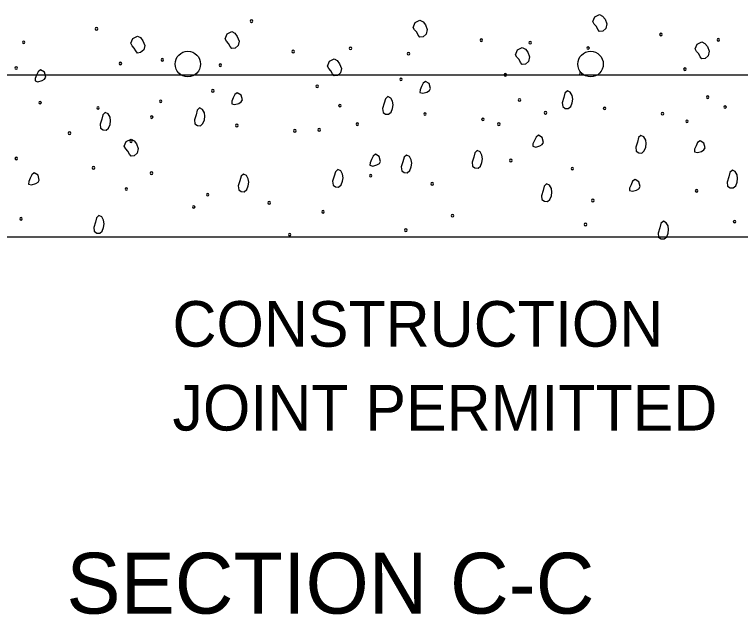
# Model space of a CAD drawing. Extents: x -439.1 to -407.9, y -458.1 to -436.2.
# Drawn here: x -421.545 to -419.155, y -450.306 to -448.332 of the extents above; entities that cross this region are included whole.
import ezdxf

# ---------------------------------------------------------------- set-up
doc = ezdxf.new("R2010")
doc.units = 0
doc.layers.add('Level 4', color=7, linetype='Continuous')

msp = doc.modelspace()

# ---------------------------------------------------------------- linework, layer by layer
at = {"layer": 'Level 4'}
for p, q in [((-423.8016, -448.5298), (-417.0312, -448.5298)), ((-423.8016, -449.0632), (-416.8905, -449.0632))]:
    msp.add_line(p, q, dxfattribs=at)
for points in [[(-420.2324, -448.3737), (-420.2258, -448.3579), (-420.2103, -448.3503), (-420.2, -448.3552), (-420.1921, -448.3659), (-420.1864, -448.3811), (-420.1896, -448.3957), (-420.1996, -448.4046), (-420.2103, -448.4061), (-420.2158, -448.3991), (-420.2207, -448.3892), (-420.2277, -448.3817), (-420.2324, -448.3737)], [(-419.6411, -448.3549), (-419.6345, -448.3392), (-419.619, -448.3315), (-419.6087, -448.3364), (-419.6008, -448.3471), (-419.5951, -448.3624), (-419.5982, -448.377), (-419.6083, -448.3858), (-419.619, -448.3873), (-419.6244, -448.3803), (-419.6294, -448.3705), (-419.6364, -448.3629), (-419.6411, -448.3549)], [(-420.8519, -448.4112), (-420.8453, -448.3955), (-420.8298, -448.3878), (-420.8195, -448.3927), (-420.8116, -448.4034), (-420.8059, -448.4187), (-420.809, -448.4333), (-420.8191, -448.4421), (-420.8298, -448.4437), (-420.8353, -448.4366), (-420.8402, -448.4268), (-420.8472, -448.4192), (-420.8519, -448.4112)], [(-421.1625, -448.4261), (-421.1559, -448.4104), (-421.1404, -448.4028), (-421.1301, -448.4076), (-421.1222, -448.4183), (-421.1165, -448.4336), (-421.1196, -448.4482), (-421.1297, -448.457), (-421.1404, -448.4586), (-421.1459, -448.4515), (-421.1508, -448.4417), (-421.1578, -448.4341), (-421.1625, -448.4261)], [(-419.304, -448.4449), (-419.2974, -448.4292), (-419.2819, -448.4215), (-419.2717, -448.4264), (-419.2638, -448.4371), (-419.2581, -448.4524), (-419.2612, -448.467), (-419.2712, -448.4758), (-419.2819, -448.4774), (-419.2874, -448.4703), (-419.2923, -448.4605), (-419.2993, -448.4529), (-419.304, -448.4449)], [(-419.8953, -448.4637), (-419.8888, -448.4479), (-419.8733, -448.4403), (-419.863, -448.4452), (-419.8551, -448.4559), (-419.8494, -448.4711), (-419.8525, -448.4857), (-419.8626, -448.4946), (-419.8733, -448.4961), (-419.8787, -448.4891), (-419.8837, -448.4792), (-419.8907, -448.4717), (-419.8953, -448.4637)], [(-420.5148, -448.5012), (-420.5083, -448.4855), (-420.4928, -448.4778), (-420.4825, -448.4827), (-420.4746, -448.4934), (-420.4689, -448.5087), (-420.472, -448.5233), (-420.482, -448.5321), (-420.4928, -448.5337), (-420.4982, -448.5266), (-420.5032, -448.5168), (-420.5102, -448.5092), (-420.5148, -448.5012)], [(-421.4593, -448.5139), (-421.4671, -448.5198), (-421.4723, -448.5308), (-421.477, -448.542), (-421.4775, -448.5502), (-421.468, -448.5526), (-421.4541, -448.5489), (-421.4463, -448.5442), (-421.4424, -448.5373), (-421.4467, -448.5213), (-421.4593, -448.5139)], [(-420.1922, -448.5514), (-420.1999, -448.5573), (-420.2051, -448.5683), (-420.2099, -448.5795), (-420.2103, -448.5878), (-420.2009, -448.5901), (-420.187, -448.5865), (-420.1792, -448.5817), (-420.1753, -448.5748), (-420.1795, -448.5589), (-420.1922, -448.5514)], [(-420.8116, -448.589), (-420.8194, -448.5949), (-420.8246, -448.6058), (-420.8294, -448.6171), (-420.8298, -448.6253), (-420.8203, -448.6277), (-420.8065, -448.624), (-420.7987, -448.6193), (-420.7948, -448.6123), (-420.799, -448.5964), (-420.8116, -448.589)], [(-419.7247, -448.5828), (-419.7326, -448.5902), (-419.7363, -448.6048), (-419.7416, -448.6216), (-419.7402, -448.6347), (-419.732, -448.6403), (-419.7221, -448.6412), (-419.7136, -448.6338), (-419.7091, -448.6217), (-419.7073, -448.61), (-419.7091, -448.5983), (-419.7151, -448.5875), (-419.7247, -448.5828)], [(-420.316, -448.6015), (-420.3239, -448.609), (-420.3277, -448.6236), (-420.333, -448.6404), (-420.3316, -448.6535), (-420.3234, -448.6591), (-420.3134, -448.6599), (-420.305, -448.6526), (-420.3004, -448.6405), (-420.2986, -448.6287), (-420.3004, -448.6171), (-420.3064, -448.6063), (-420.316, -448.6015)], [(-421.2461, -448.654), (-421.254, -448.6614), (-421.2578, -448.6761), (-421.2631, -448.6928), (-421.2617, -448.7059), (-421.2535, -448.7115), (-421.2435, -448.7124), (-421.2351, -448.705), (-421.2305, -448.6929), (-421.2287, -448.6812), (-421.2305, -448.6696), (-421.2365, -448.6588), (-421.2461, -448.654)], [(-420.9355, -448.6391), (-420.9434, -448.6465), (-420.9472, -448.6611), (-420.9525, -448.6779), (-420.9511, -448.691), (-420.9429, -448.6966), (-420.9329, -448.6975), (-420.9245, -448.6901), (-420.9199, -448.678), (-420.9181, -448.6663), (-420.9199, -448.6547), (-420.9259, -448.6438), (-420.9355, -448.6391)], [(-419.8202, -448.7289), (-419.828, -448.7348), (-419.8332, -448.7458), (-419.838, -448.757), (-419.8384, -448.7652), (-419.8289, -448.7676), (-419.815, -448.7639), (-419.8073, -448.7592), (-419.8034, -448.7523), (-419.8076, -448.7363), (-419.8202, -448.7289)], [(-419.4824, -448.7291), (-419.4903, -448.7365), (-419.4941, -448.7512), (-419.4994, -448.7679), (-419.498, -448.781), (-419.4898, -448.7866), (-419.4798, -448.7875), (-419.4714, -448.7801), (-419.4668, -448.768), (-419.465, -448.7563), (-419.4668, -448.7447), (-419.4728, -448.7339), (-419.4824, -448.7291)], [(-421.1835, -448.7651), (-421.177, -448.7494), (-421.1615, -448.7417), (-421.1512, -448.7466), (-421.1433, -448.7573), (-421.1376, -448.7726), (-421.1407, -448.7872), (-421.1508, -448.796), (-421.1615, -448.7975), (-421.1669, -448.7905), (-421.1719, -448.7807), (-421.1789, -448.7731), (-421.1835, -448.7651)], [(-419.2881, -448.7469), (-419.2959, -448.7528), (-419.3011, -448.7638), (-419.3059, -448.775), (-419.3063, -448.7832), (-419.2968, -448.7856), (-419.2829, -448.7819), (-419.2752, -448.7772), (-419.2712, -448.7703), (-419.2755, -448.7543), (-419.2881, -448.7469)], [(-420.0216, -448.779), (-420.0295, -448.7864), (-420.0333, -448.8011), (-420.0386, -448.8178), (-420.0372, -448.8309), (-420.029, -448.8365), (-420.019, -448.8374), (-420.0106, -448.83), (-420.006, -448.8179), (-420.0042, -448.8062), (-420.006, -448.7946), (-420.012, -448.7838), (-420.0216, -448.779)], [(-420.3568, -448.7913), (-420.3646, -448.7972), (-420.3698, -448.8082), (-420.3745, -448.8194), (-420.3749, -448.8276), (-420.3655, -448.83), (-420.3516, -448.8263), (-420.3438, -448.8216), (-420.3399, -448.8147), (-420.3441, -448.7987), (-420.3568, -448.7913)], [(-420.2547, -448.7939), (-420.2626, -448.8014), (-420.2663, -448.816), (-420.2717, -448.8328), (-420.2702, -448.8458), (-420.2621, -448.8514), (-420.2521, -448.8523), (-420.2436, -448.845), (-420.2391, -448.8329), (-420.2373, -448.8211), (-420.2391, -448.8095), (-420.2451, -448.7987), (-420.2547, -448.7939)], [(-421.4804, -448.8528), (-421.4881, -448.8587), (-421.4933, -448.8697), (-421.4981, -448.881), (-421.4985, -448.8892), (-421.4891, -448.8915), (-421.4752, -448.8879), (-421.4674, -448.8831), (-421.4635, -448.8762), (-421.4677, -448.8603), (-421.4804, -448.8528)], [(-420.4806, -448.8414), (-420.4885, -448.8488), (-420.4923, -448.8635), (-420.4976, -448.8802), (-420.4962, -448.8933), (-420.488, -448.8989), (-420.478, -448.8998), (-420.4696, -448.8924), (-420.465, -448.8803), (-420.4632, -448.8686), (-420.465, -448.857), (-420.471, -448.8462), (-420.4806, -448.8414)], [(-419.1816, -448.8438), (-419.1895, -448.8513), (-419.1933, -448.8659), (-419.1986, -448.8827), (-419.1972, -448.8958), (-419.189, -448.9013), (-419.179, -448.9022), (-419.1706, -448.8949), (-419.166, -448.8828), (-419.1642, -448.871), (-419.166, -448.8594), (-419.172, -448.8486), (-419.1816, -448.8438)], [(-420.7912, -448.8563), (-420.7991, -448.8637), (-420.8029, -448.8784), (-420.8082, -448.8951), (-420.8068, -448.9082), (-420.7986, -448.9138), (-420.7886, -448.9147), (-420.7802, -448.9073), (-420.7756, -448.8953), (-420.7738, -448.8835), (-420.7756, -448.8719), (-420.7816, -448.8611), (-420.7912, -448.8563)], [(-419.5021, -448.8745), (-419.5099, -448.8804), (-419.5151, -448.8914), (-419.5198, -448.9027), (-419.5203, -448.9109), (-419.5108, -448.9132), (-419.4969, -448.9096), (-419.4891, -448.9048), (-419.4852, -448.8979), (-419.4895, -448.882), (-419.5021, -448.8745)], [(-419.793, -448.8887), (-419.8009, -448.8962), (-419.8047, -448.9108), (-419.81, -448.9276), (-419.8086, -448.9406), (-419.8004, -448.9462), (-419.7904, -448.9471), (-419.782, -448.9397), (-419.7774, -448.9277), (-419.7756, -448.9159), (-419.7774, -448.9043), (-419.7834, -448.8935), (-419.793, -448.8887)], [(-421.2671, -448.993), (-421.2751, -449.0004), (-421.2788, -449.015), (-421.2841, -449.0318), (-421.2827, -449.0449), (-421.2745, -449.0505), (-421.2645, -449.0514), (-421.2561, -449.044), (-421.2516, -449.0319), (-421.2497, -449.0202), (-421.2516, -449.0085), (-421.2576, -448.9977), (-421.2671, -448.993)], [(-419.4087, -449.0117), (-419.4166, -449.0192), (-419.4204, -449.0338), (-419.4257, -449.0506), (-419.4243, -449.0636), (-419.4161, -449.0692), (-419.4061, -449.0701), (-419.3977, -449.0628), (-419.3931, -449.0507), (-419.3913, -449.0389), (-419.3931, -449.0273), (-419.3991, -449.0165), (-419.4087, -449.0117)]]:
    msp.add_lwpolyline(points, close=True, dxfattribs=at)
for centre in [(-420.9744, -448.4946), (-419.6484, -448.4946)]:
    msp.add_circle(centre, 0.042, dxfattribs=at)
for centre, start, end in [((-420.7647, -448.3531), 0, 180), ((-421.2752, -448.3785), 0, 180), ((-420.7647, -448.3531), 180, 0), ((-421.2752, -448.3785), 180, 0), ((-419.4168, -448.3972), 0, 180), ((-419.4168, -448.3972), 180, 0), ((-421.5151, -448.4229), 0, 180), ((-421.5151, -448.4229), 180, 0), ((-420.0081, -448.416), 0, 180), ((-420.0081, -448.416), 180, 0), ((-419.8474, -448.4242), 0, 180), ((-419.2279, -448.4148), 0, 180), ((-419.2279, -448.4148), 180, 0), ((-420.4387, -448.4429), 0, 180), ((-420.4387, -448.4429), 180, 0), ((-419.8474, -448.4242), 180, 0), ((-419.6566, -448.4417), 0, 180), ((-419.6566, -448.4417), 180, 0), ((-420.6276, -448.4535), 0, 180), ((-420.6276, -448.4535), 180, 0), ((-420.248, -448.4605), 0, 180), ((-420.248, -448.4605), 180, 0), ((-421.1963, -448.4925), 0, 180), ((-421.1963, -448.4925), 180, 0), ((-421.0582, -448.4805), 0, 180), ((-421.0582, -448.4805), 180, 0), ((-420.8675, -448.498), 0, 180), ((-421.5397, -448.5075), 0, 180), ((-421.5397, -448.5075), 180, 0), ((-420.8675, -448.498), 180, 0), ((-419.3378, -448.5113), 0, 180), ((-419.3378, -448.5113), 180, 0), ((-420.2726, -448.545), 0, 180), ((-419.9292, -448.53), 0, 180), ((-419.9292, -448.53), 180, 0), ((-419.6812, -448.5262), 0, 180), ((-419.6812, -448.5262), 180, 0), ((-420.5486, -448.5676), 0, 180), ((-420.2726, -448.545), 180, 0), ((-420.892, -448.5826), 0, 180), ((-420.892, -448.5826), 180, 0), ((-420.5486, -448.5676), 180, 0), ((-421.064, -448.6171), 0, 180), ((-419.8824, -448.6126), 0, 180), ((-419.8824, -448.6126), 180, 0), ((-419.2629, -448.6033), 0, 180), ((-419.2629, -448.6033), 180, 0), ((-421.4608, -448.6215), 0, 180), ((-421.4608, -448.6215), 180, 0), ((-421.27, -448.639), 0, 180), ((-421.064, -448.6171), 180, 0), ((-420.4737, -448.6314), 0, 180), ((-420.4737, -448.6314), 180, 0), ((-419.6023, -448.6403), 0, 180), ((-419.2055, -448.6359), 0, 180), ((-419.2055, -448.6359), 180, 0), ((-421.27, -448.639), 180, 0), ((-420.1936, -448.659), 0, 180), ((-420.1936, -448.659), 180, 0), ((-419.7969, -448.6547), 0, 180), ((-419.7969, -448.6547), 180, 0), ((-419.6023, -448.6403), 180, 0), ((-419.4115, -448.6578), 0, 180), ((-419.4115, -448.6578), 180, 0), ((-421.0932, -448.669), 0, 180), ((-421.0932, -448.669), 180, 0), ((-420.0029, -448.6766), 0, 180), ((-420.0029, -448.6766), 180, 0), ((-419.3311, -448.6829), 0, 180), ((-419.3311, -448.6829), 180, 0), ((-420.8131, -448.6966), 0, 180), ((-420.8131, -448.6966), 180, 0), ((-420.6223, -448.7141), 0, 180), ((-420.5419, -448.7111), 0, 180), ((-420.4163, -448.6922), 0, 180), ((-420.4163, -448.6922), 180, 0), ((-419.9505, -448.6923), 0, 180), ((-419.9505, -448.6923), 180, 0), ((-421.3639, -448.7219), 0, 180), ((-421.3639, -448.7219), 180, 0), ((-420.6223, -448.7141), 180, 0), ((-420.5419, -448.7111), 180, 0), ((-421.1614, -448.7486), 0, 180), ((-421.1614, -448.7486), 180, 0), ((-421.5393, -448.8051), 0, 180), ((-421.5393, -448.8051), 180, 0), ((-419.9108, -448.812), 0, 180), ((-419.9108, -448.812), 180, 0), ((-421.285, -448.836), 0, 180), ((-421.285, -448.836), 180, 0), ((-421.0942, -448.8535), 0, 180), ((-421.0942, -448.8535), 180, 0), ((-419.7083, -448.8387), 0, 180), ((-419.7083, -448.8387), 180, 0), ((-420.3725, -448.8619), 0, 180), ((-420.3725, -448.8619), 180, 0), ((-420.1699, -448.8886), 0, 180), ((-420.1699, -448.8886), 180, 0), ((-421.1769, -448.9058), 0, 180), ((-421.1769, -448.9058), 180, 0), ((-420.909, -448.9243), 0, 180), ((-420.909, -448.9243), 180, 0), ((-419.2994, -448.9118), 0, 180), ((-419.2994, -448.9118), 180, 0), ((-420.7065, -448.951), 0, 180), ((-419.6411, -448.9435), 0, 180), ((-419.6411, -448.9435), 180, 0), ((-420.9549, -448.9647), 0, 180), ((-420.9549, -448.9647), 180, 0), ((-420.7065, -448.951), 180, 0), ((-420.5292, -448.9809), 0, 180), ((-420.5292, -448.9809), 180, 0), ((-420.1028, -448.9934), 0, 180), ((-420.1028, -448.9934), 180, 0), ((-421.5236, -449.0037), 0, 180), ((-421.5236, -449.0037), 180, 0), ((-419.6652, -449.0224), 0, 180), ((-419.1743, -449.0131), 0, 180), ((-419.1743, -449.0131), 180, 0), ((-420.2565, -449.0412), 0, 180), ((-420.2565, -449.0412), 180, 0), ((-419.6652, -449.0224), 180, 0), ((-420.6393, -449.0558), 0, 180), ((-420.6393, -449.0558), 180, 0)]:
    msp.add_arc(centre, 0.00416, start, end, dxfattribs=at)

# ---------------------------------------------------------------- texts
for s, height, p in [('CONSTRUCTION ', 0.15, (-421.0249, -449.4245)), ('CONSTRUCTION ', 0.15, (-421.0249, -449.4245)), ('JOINT PERMITTED', 0.15, (-421.0249, -449.7005)), ('JOINT PERMITTED', 0.15, (-421.0249, -449.7005)), ('SECTION C-C', 0.2, (-421.3743, -450.3028))]:
    msp.add_text(s, height=height, dxfattribs=at).set_placement(p)

doc.saveas('drawing.dxf')
